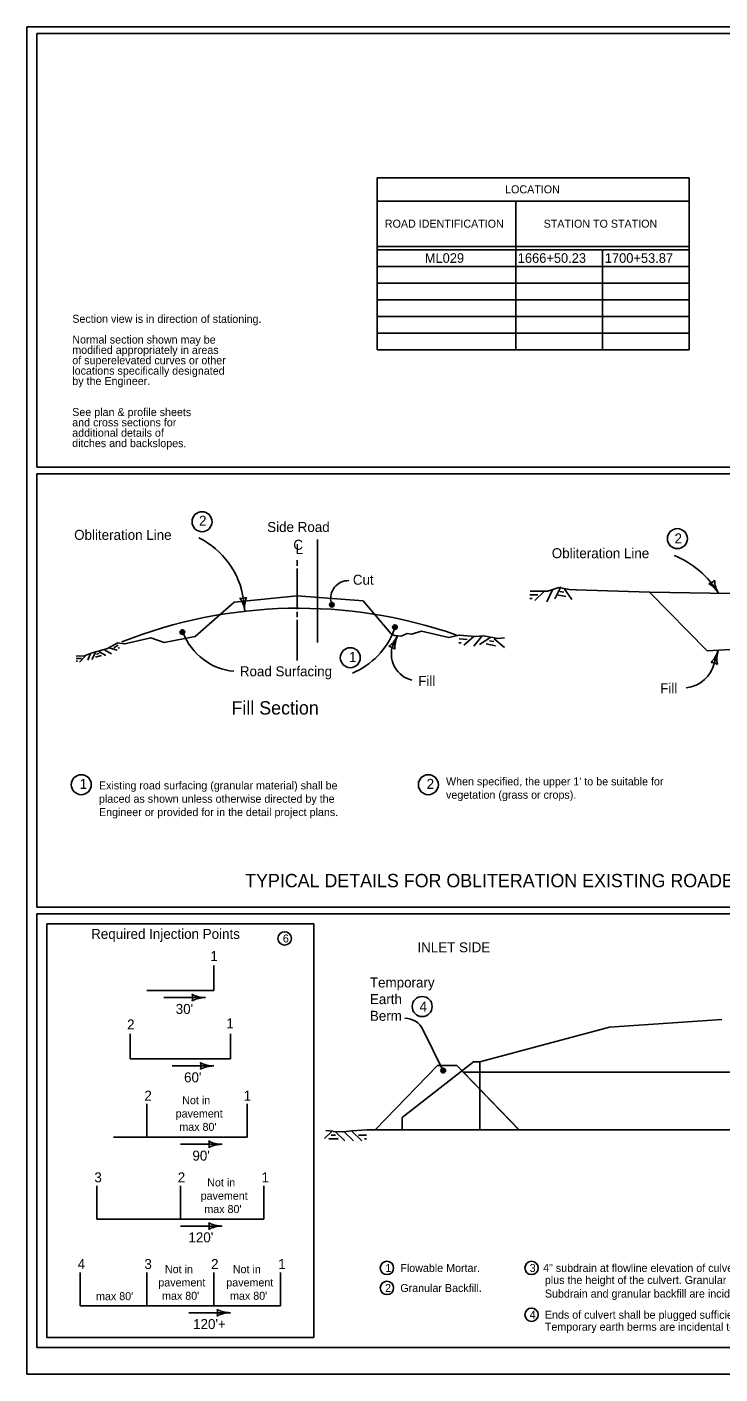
# Model space of a CAD drawing. Extents: x 10133 to 81668, y 7924 to 11018.
# Drawn here: x 10133 to 11172, y 7924 to 9944 of the extents above; entities that cross this region are included whole.
import ezdxf

# ---------------------------------------------------------------- set-up
doc = ezdxf.new("R2010")
doc.units = 0
for name, color, linetype in [('dsnCellElements', 7, 'Continuous'), ('DsnShtMinorGrid07', 7, 'Continuous'), ('DsnShtMinorGrid08', 7, 'Continuous'), ('DsnShtMinorGrid14', 7, 'Continuous'), ('Level 10', 7, 'Continuous'), ('Level 12', 7, 'Continuous'), ('Level 5', 7, 'Continuous'), ('Level 6', 7, 'Continuous'), ('Level 7', 7, 'Continuous'), ('Level 8', 7, 'Continuous'), ('SheetAddendum', 7, 'Continuous'), ('SheetBorder', 7, 'Continuous'), ('ShtPlotIdentification', 7, 'Continuous')]:
    doc.layers.add(name, color=color, linetype=linetype)

msp = doc.modelspace()

# ---------------------------------------------------------------- linework, layer by layer
at = {"layer": 'dsnCellElements'}
for p, q in [((10568, 9175.6), (10568, 9021.1)), ((10457.1, 9085.5), (10459.1, 9068.2)), ((10680.1, 9013.9), (10688, 9031)), ((11163.3, 8991.1), (11168.8, 9008.8)), ((10811.4, 8392.2), (11005.8, 8444.1)), ((11005.8, 8444.1), (11174.4, 8455.9)), ((10756.6, 8378.6), (10726.1, 8440.8)), ((10654.8, 8290.1), (10748.1, 8386.7)), ((10694.9, 8308.9), (10801.9, 8392.2)), ((10777.2, 8386.7), (10748.1, 8386.7)), ((10870.7, 8289.9), (10777.2, 8386.7)), ((10801.9, 8392.2), (10811.4, 8392.2)), ((10811.4, 8376.7), (10811.4, 8392.2)), ((10786.9, 8376.7), (11949.3, 8376.7)), ((10811.4, 8376.7), (10811.3, 8290.1)), ((10695, 8290), (10695, 8308.9)), ((10589.4, 8287.9), (10578.6, 8277.1)), ((10591.5, 8288), (10580.6, 8289)), ((10588.8, 8282.4), (10595.3, 8282.4)), ((10595.3, 8282.4), (10588.8, 8282.4)), ((10605.6, 8287.3), (10591.7, 8287.9)), ((10594.8, 8287.9), (10608.9, 8273.8)), ((10619.5, 8288.7), (10606.4, 8287.3)), ((10607.8, 8287.7), (10621.9, 8273.6)), ((10642.2, 8290.1), (10619.7, 8288.7)), ((10620.2, 8287.9), (10634.4, 8273.8)), ((10629.8, 8282.4), (10641.8, 8282.4)), ((10632.8, 8282.4), (10632.8, 8282.4)), ((10642.2, 8290.1), (12126.8, 8290.1)), ((10585, 8276.6), (10599.2, 8276.6)), ((10599.2, 8276.6), (10585, 8276.6)), ((10638.6, 8276.6), (10638.6, 8276.6)), ((10638.6, 8276.6), (10641.8, 8276.6))]:
    msp.add_line(p, q, dxfattribs=at)
for points in [[(10267.7, 9020.1), (10268.5, 9020.6), (10279.4, 9018.9), (10318.4, 9027.9), (10338, 9021), (10384.6, 9030), (10443.1, 9081.5), (10537.4, 9090.9), (10636.5, 9083.7), (10678.1, 9034.7), (10683.8, 9031.3), (10693.5, 9030.7), (10702.5, 9034.7), (10709.2, 9033.7), (10724, 9038.2), (10764.9, 9028.3), (10780.5, 9032), (10780.7, 9032)], [(10886.8, 9098.1), (10913.2, 9097.8), (10929.8, 9103.6), (10945.5, 9100.4), (10956, 9100.1)], [(10886.8, 9098.1), (10913.2, 9097.8), (10929.8, 9103.6), (10945.5, 9100.4), (10956.5, 9100.1)], [(10886.8, 9098.1), (10913.2, 9097.8), (10929.8, 9103.6), (10945.5, 9100.4), (10954.8, 9100.1)], [(10956, 9100.1), (11066, 9096.7), (11152.4, 9008.5), (11187.1, 9010.5), (11217.9, 9039), (11317.8, 9050.7), (11414.7, 9040.8), (11452.3, 9000.4), (11485.2, 8997.3), (11565.8, 9087.3), (11687.7, 9081.1)], [(10780.5, 9032), (10804.3, 9029.9), (10817.4, 9031.2), (10838, 9026.8), (10848.7, 9027.9)], [(10781.1, 9031.9), (10804.3, 9029.9), (10817.4, 9031.2), (10838, 9026.8), (10848.7, 9027.9)], [(10206.1, 9000.5), (10218.6, 9001), (10228.9, 9005), (10253.4, 9012.1), (10267.7, 9020.1)], [(10757, 8382.3), (10755.8, 8381.8), (10754, 8381.2), (10753.6, 8379.4), (10753.9, 8377.7), (10755.1, 8376.2), (10756.8, 8376.4), (10758.7, 8376.6), (10759.5, 8378.1), (10759.7, 8379.7), (10758.6, 8381.7), (10757.3, 8381.9), (10755.4, 8381.4), (10753.9, 8380.2), (10754, 8378.5), (10755.1, 8377.1), (10756.8, 8376.9), (10758.6, 8377.3), (10758.9, 8378.3), (10759.3, 8379.5), (10758.4, 8381.1), (10757.1, 8381), (10755.6, 8380.8), (10754.4, 8379.9), (10755, 8378.4), (10756.2, 8377.5), (10757.7, 8377.4), (10758.1, 8378.3), (10758.6, 8379.2), (10757.8, 8380.4), (10756.7, 8380.7), (10755.7, 8380.2), (10755.6, 8379), (10756.1, 8378.2), (10757.2, 8377.9), (10757.7, 8378.4), (10758, 8379), (10757.4, 8379.9), (10756.7, 8380.1), (10756, 8379.7), (10756.1, 8379), (10756.6, 8378.6), (10757.4, 8378.7), (10757.3, 8379.2), (10756.7, 8379.5)]]:
    msp.add_lwpolyline(points, dxfattribs=at)
for centre, radius in [((10518.9, 8577.2), 10), ((10725, 8475.1), 15), ((10756.7, 8379.1), 3.5), ((10672.3, 8083.1), 10), ((10889, 8083.1), 10), ((10672.3, 8053.1), 10), ((10889, 8013), 10)]:
    msp.add_circle(centre, radius, dxfattribs=at)
for centre, radius, start, end in [((10364.4, 8488.5), 16.4, 342.2666, 17.7333), ((10400, 8531), 42.5, 241.9275, 270), ((10400, 8446), 42.5, 90, 118.0725), ((10699.2, 8427.5), 30, 26.1603, 90), ((10376.9, 8386), 16.4, 342.2666, 17.7333), ((10412.5, 8428.5), 42.5, 241.9275, 270), ((10412.5, 8343.5), 42.5, 90, 118.0725), ((10592, 8292.9), 5, 264.4618, 267.1527), ((10605.9, 8292.2), 5, 267.1527, 275.9854), ((10620, 8283.7), 5, 93.5449, 95.9854), ((10389.4, 8268.5), 16.4, 342.2666, 17.7333), ((10425, 8311), 42.5, 241.9275, 270), ((10425, 8226), 42.5, 90, 118.0725), ((10389.4, 8146), 16.4, 342.2666, 17.7333), ((10425, 8188.5), 42.5, 241.9275, 270), ((10425, 8103.5), 42.5, 90, 118.0725), ((10401.9, 8016), 16.4, 342.2666, 17.7333), ((10437.5, 8058.5), 42.5, 241.9275, 270), ((10437.5, 7973.5), 42.5, 90, 118.0725)]:
    msp.add_arc(centre, radius, start, end, dxfattribs=at)
at = {"layer": 'DsnShtMinorGrid07'}
for p, q in [((10657.5, 9718), (11125.5, 9718)), ((10657.5, 9460), (10657.5, 9718)), ((11125.5, 9610), (11125.5, 9718)), ((10657.5, 9683), (11125.5, 9683)), ((10865.5, 9460), (10865.5, 9683)), ((10657.5, 9615), (11125.5, 9615)), ((10657.5, 9610), (10865.5, 9610)), ((10865.5, 9610), (10994.6, 9610)), ((10995.5, 9460), (10995.5, 9610)), ((10995.5, 9610), (11125.5, 9610)), ((11125.5, 9585), (11125.5, 9610)), ((10657.5, 9585), (11125.5, 9585)), ((11125.5, 9460), (11125.5, 9585)), ((10657.5, 9560), (11125.5, 9560)), ((10657.5, 9535), (11125.5, 9535)), ((10657.5, 9510), (11125.5, 9510)), ((10657.5, 9485), (11125.5, 9485)), ((10657.5, 9460), (11125.5, 9460))]:
    msp.add_line(p, q, dxfattribs=at)
at = {"layer": 'DsnShtMinorGrid08'}
msp.add_lwpolyline([(10147.5, 9934), (13252.5, 9934), (13252.5, 9284), (10147.5, 9284), (10147.5, 9934)], dxfattribs=at)
at = {"layer": 'Level 10'}
for centre, radius, start, end in [((10336.1, 9068.2), 122.3, 8.1205, 63.6379), ((11049.9, 9022), 140, 31.313, 67.8349), ((10614.6, 9086.9), 26.9, 88.6666, 193.1536), ((10451.4, 9068.1), 90.7, 201.1526, 264.3959), ((10577.1, 9079.5), 113, 292.5261, 339.8121), ((10718.8, 9003.6), 40, 165.0555, 256.3065), ((11116.2, 9001.1), 48.1, 275.6798, 348.0251)]:
    msp.add_arc(centre, radius, start, end, dxfattribs=at)
at = {"layer": 'Level 12'}
for points in [[(10147.5, 8614), (13252.5, 8614), (13252.5, 7964), (10147.5, 7964), (10147.5, 8614)], [(10811.4, 8376.7), (10786.9, 8376.7), (10811.4, 8351.4), (10811.4, 8376.7)]]:
    msp.add_lwpolyline(points, dxfattribs=at)
for points in [[(10777.2, 8386.7), (10748.1, 8386.7), (10654.8, 8290.1), (10811.3, 8290.1), (10811.4, 8351.4)], [(10777.2, 8386.7), (10748.1, 8386.7), (10654.8, 8290.1), (10811.3, 8290.1), (10811.4, 8351.4)], [(11920.8, 8335.4), (11920.8, 8376.7), (10811.4, 8376.7), (10811.4, 8351.4), (10870.5, 8290.1), (11788.7, 8290.1), (11807.3, 8309.3), (11895.6, 8309.3)], [(10811.3, 8290.1), (10870.5, 8290.1), (10811.4, 8351.4)]]:
    msp.add_lwpolyline(points, close=True, dxfattribs=at)
msp.add_circle((10756.7, 8379.1), 3.5, dxfattribs=at)
msp.add_circle((10756.7, 8379.1), 3.5, dxfattribs=at)
at = {"layer": 'Level 5'}
for points in [[(10147.5, 9274), (11692.5, 9274), (11692.5, 8624), (10147.5, 8624), (10147.5, 9274)], [(10589.3, 9074.5), (10590.5, 9075), (10592.4, 9075.6), (10592.7, 9077.4), (10592.5, 9079.1), (10591.3, 9080.6), (10589.5, 9080.4), (10587.7, 9080.2), (10586.8, 9078.7), (10586.7, 9077.1), (10587.7, 9075.1), (10589.1, 9075), (10590.9, 9075.4), (10592.4, 9076.6), (10592.4, 9078.3), (10591.2, 9079.7), (10589.6, 9079.9), (10587.7, 9079.5), (10587.4, 9078.5), (10587.1, 9077.3), (10587.9, 9075.7), (10589.3, 9075.8), (10590.8, 9076), (10591.9, 9076.9), (10591.4, 9078.4), (10590.2, 9079.3), (10588.6, 9079.4), (10588.3, 9078.5), (10587.8, 9077.6), (10588.5, 9076.4), (10589.7, 9076.1), (10590.7, 9076.6), (10590.8, 9077.8), (10590.2, 9078.6), (10589.2, 9078.9), (10588.7, 9078.4), (10588.4, 9077.8), (10588.9, 9076.9), (10589.7, 9076.7), (10590.4, 9077.2), (10590.2, 9077.8), (10589.7, 9078.2), (10589, 9078.1), (10589, 9077.6), (10589.6, 9077.3)], [(10365.2, 9033.5), (10366.4, 9034.1), (10368.2, 9034.6), (10368.6, 9036.5), (10368.3, 9038.1), (10367.2, 9039.6), (10365.4, 9039.5), (10363.6, 9039.2), (10362.7, 9037.8), (10362.5, 9036.2), (10363.6, 9034.2), (10365, 9034), (10366.8, 9034.5), (10368.3, 9035.7), (10368.3, 9037.4), (10367.1, 9038.8), (10365.4, 9039), (10363.6, 9038.6), (10363.3, 9037.6), (10362.9, 9036.3), (10363.8, 9034.8), (10365.1, 9034.9), (10366.7, 9035.1), (10367.8, 9036), (10367.2, 9037.5), (10366.1, 9038.4), (10364.5, 9038.4), (10364.1, 9037.6), (10363.7, 9036.7), (10364.4, 9035.4), (10365.6, 9035.2), (10366.6, 9035.7), (10366.6, 9036.8), (10366.1, 9037.7), (10365.1, 9037.9), (10364.6, 9037.5), (10364.3, 9036.9), (10364.8, 9036), (10365.5, 9035.8), (10366.2, 9036.2), (10366.1, 9036.8), (10365.6, 9037.2), (10364.9, 9037.2), (10364.9, 9036.7), (10365.5, 9036.4)], [(10684, 9040.8), (10685.2, 9041.3), (10687, 9041.9), (10687.4, 9043.8), (10687.1, 9045.4), (10685.9, 9046.9), (10684.2, 9046.8), (10682.4, 9046.5), (10681.5, 9045), (10681.3, 9043.5), (10682.4, 9041.5), (10683.7, 9041.3), (10685.6, 9041.8), (10687.1, 9042.9), (10687, 9044.7), (10685.9, 9046.1), (10684.2, 9046.2), (10682.4, 9045.9), (10682.1, 9044.8), (10681.7, 9043.6), (10682.6, 9042.1), (10683.9, 9042.1), (10685.5, 9042.4), (10686.6, 9043.2), (10686, 9044.8), (10684.8, 9045.6), (10683.3, 9045.7), (10682.9, 9044.9), (10682.4, 9043.9), (10683.2, 9042.7), (10684.3, 9042.4), (10685.3, 9043), (10685.4, 9044.1), (10684.9, 9044.9), (10683.8, 9045.2), (10683.3, 9044.8), (10683, 9044.2), (10683.6, 9043.2), (10684.3, 9043.1), (10685, 9043.5), (10684.9, 9044.1), (10684.4, 9044.5), (10683.6, 9044.5), (10683.7, 9044), (10684.3, 9043.7)]]:
    msp.add_lwpolyline(points, dxfattribs=at)
for centre, radius in [((10395, 9202.1), 15), ((11107.7, 9176.7), 15), ((10589.6, 9077.7), 3.5), ((10365.5, 9036.7), 3.5), ((10684.3, 9044), 3.5), ((10617.3, 8998.2), 15), ((10214, 8807.8), 15), ((10734.3, 8807.8), 15)]:
    msp.add_circle(centre, radius, dxfattribs=at)
for centre, radius, start, end in [((11151, 9125.2), 16.4, 283.5797, 319.0464), ((11205.8, 9116.8), 42.5, 183.2405, 211.313), ((11133.2, 9072.7), 42.5, 31.313, 59.3855), ((10455, 9103.6), 16.4, 258.8775, 294.3443), ((10416.9, 9063.3), 42.5, 6.6109, 34.6834), ((10501.3, 9073.1), 42.5, 158.5384, 186.6109), ((10649.3, 9048.7), 42.5, 307.3638, 335.4363), ((10726.6, 9013.4), 42.5, 155.4363, 183.5088), ((10673.2, 8998.6), 16.4, 47.7029, 83.1696), ((11128.2, 9021.4), 42.5, 314.7357, 342.8082), ((11158.3, 8974.8), 16.4, 55.0749, 90.5416), ((11209.4, 8996.3), 42.5, 162.8082, 190.8807)]:
    msp.add_arc(centre, radius, start, end, dxfattribs=at)
at = {"layer": 'SheetAddendum'}
for p, q in [((10908.4, 9097.8), (10894.1, 9083.9)), ((10920.5, 9100.1), (10911.8, 9082.1)), ((10932.7, 9104.6), (10924, 9086.6)), ((10938.1, 9101.9), (10949.2, 9085.3)), ((10802.7, 9030.1), (10787.4, 9017.2)), ((10815.1, 9030.8), (10802.4, 9015.3)), ((10247.7, 9010.3), (10259.2, 9003.9)), ((10255.3, 9013.2), (10268, 9009.6)), ((10827.8, 9029), (10811, 9018.1)), ((10833, 9026.3), (10848.5, 9013.7)), ((10220.3, 9001), (10211.4, 8991.4)), ((10227.9, 9004.4), (10223.6, 8994.6)), ((10236, 9007.1), (10229.7, 8995.5)), ((10239.4, 9008), (10251, 9001.7))]:
    msp.add_line(p, q, dxfattribs=at)
for points in [[(10886.7, 9092.7), (10898.7, 9092.5)], [(10927.6, 9092.4), (10940.2, 9089.9)], [(10931.2, 9097.7), (10937.6, 9096.4)], [(10886.6, 9086.9), (10889.9, 9086.8)], [(10262.6, 9013.1), (10269.5, 9017)], [(10269.5, 9012.6), (10271.3, 9013.7)], [(10780.2, 9020.7), (10783.4, 9020.4)], [(10780.7, 9026.5), (10792.6, 9025.4)], [(10821.1, 9018.8), (10835, 9015.8)], [(10826.1, 9023.7), (10832.5, 9022.4)], [(10206.3, 8996.9), (10214.2, 8997.2)], [(10206.4, 8993.1), (10208.5, 8993.2)], [(10235.3, 8999.1), (10244.3, 9001.7)], [(10236.7, 9003.5), (10240.8, 9004.7)]]:
    msp.add_lwpolyline(points, dxfattribs=at)
at = {"layer": 'SheetBorder'}
msp.add_lwpolyline([(10132.5, 9944), (13267.5, 9944), (13267.5, 7924), (10132.5, 7924)], close=True, dxfattribs=at)
at = {"layer": 'ShtPlotIdentification'}
for p, q in [((11066, 9096.7), (11565.8, 9087.3)), ((10412.5, 8499), (10412.5, 8536.5)), ((10312.5, 8499), (10412.5, 8499)), ((10337.5, 8488.5), (10400, 8488.5)), ((10287.5, 8396.5), (10287.5, 8434)), ((10437.5, 8396.5), (10437.5, 8434)), ((10287.5, 8396.5), (10437.5, 8396.5)), ((10350, 8386), (10412.5, 8386)), ((10312.5, 8279), (10312.5, 8329)), ((10462.5, 8279), (10462.5, 8329)), ((10262.5, 8279), (10462.5, 8279)), ((10362.5, 8268.5), (10425, 8268.5)), ((10237.5, 8156.5), (10237.5, 8206.5)), ((10362.5, 8156.5), (10362.5, 8206.5)), ((10487.5, 8156.5), (10487.5, 8206.5)), ((10237.5, 8156.5), (10487.5, 8156.5)), ((10362.5, 8146), (10425, 8146)), ((10212.5, 8026.5), (10212.5, 8076.5)), ((10312.5, 8026.5), (10312.5, 8076.5)), ((10412.5, 8026.5), (10412.5, 8076.5)), ((10512.5, 8026.5), (10512.5, 8076.5)), ((10212.5, 8026.5), (10512.5, 8026.5)), ((10375, 8016), (10437.5, 8016))]:
    msp.add_line(p, q, dxfattribs=at)
for points in [[(10537.4, 9136.2), (10537.4, 9144.3)], [(10537.4, 9071.1), (10537.4, 9132.1)], [(10537.4, 9058.9), (10537.4, 9067.1)], [(10537.4, 8993.9), (10537.4, 9054.9)]]:
    msp.add_lwpolyline(points, dxfattribs=at)
msp.add_lwpolyline([(10162.5, 7979), (10562.5, 7979), (10562.5, 8599), (10162.5, 8599)], close=True, dxfattribs=at)
for centre, radius, start, end in [((10539.4, 8353.7), 718.7, 70.7273, 111.6141), ((10614.6, 9086.9), 26.9, 198.1595, 198.2767), ((10336.1, 9068.2), 122.3, 359.276, 359.2887)]:
    msp.add_arc(centre, radius, start, end, dxfattribs=at)

# ---------------------------------------------------------------- texts
at = {"layer": 'DsnShtMinorGrid07'}
for s, p in [('LOCATION', (10849.4, 9694.5)), ('ROAD IDENTIFICATION', (10669.1, 9643)), ('STATION TO STATION', (10907.2, 9643))]:
    msp.add_text(s, height=12, dxfattribs=at).set_placement(p)
at = {"layer": 'DsnShtMinorGrid14'}
for s, p in [('Section view is in direction of stationing.', (10200.5, 9500.4)), ('Normal section shown may be', (10200.5, 9469.3)), ('modified appropriately in areas', (10200.5, 9453.8)), ('of superelevated curves or other', (10200.5, 9438.3)), ('locations specifically designated', (10200.5, 9422.7)), ('by the Engineer.', (10200.5, 9407.2)), ('See plan & profile sheets', (10200.4, 9360.6)), ('and cross sections for', (10200.4, 9345.1)), ('additional details of', (10200.4, 9329.6)), ('ditches and backslopes.', (10200.4, 9314))]:
    msp.add_text(s, height=12, rotation=359.9583, dxfattribs=at).set_placement(p)
at = {"layer": 'Level 6'}
for s, p in [('Fill Section', (10439.2, 8913)), ('TYPICAL DETAILS FOR OBLITERATION EXISTING ROADBED', (10459.7, 8654))]:
    msp.add_text(s, height=19.999, dxfattribs=at).set_placement(p)
at = {"layer": 'Level 7'}
for s, p in [('2', (10390.5, 9196)), ('Side Road', (10492.7, 9186.7)), ('Obliteration Line', (10203.3, 9174.9)), ('C', (10531.9, 9160)), ('2', (11103.4, 9169.5)), ('L', (10535.4, 9153.7)), ('Obliteration Line', (10919.4, 9147.4)), ('Cut', (10621.1, 9107.6)), ('1', (10615.3, 8991.6)), ('Road Surfacing', (10451.7, 8970.3)), ('Fill', (10719.1, 8955.9)), ('Fill', (11081.9, 8944.8)), ('1', (10211.5, 8801.5)), ('2', (10731.8, 8801.5))]:
    msp.add_text(s, height=15, dxfattribs=at).set_placement(p)
at = {"layer": 'Level 8'}
for s, p in [('Existing road surfacing (granular material) shall be', (10240.5, 8800.7)), ("When specified, the upper 1' to be suitable for", (10760.8, 8806.7)), ('placed as shown unless otherwise directed by the', (10240.5, 8780.7)), ('vegetation (grass or crops).', (10760.8, 8786.7)), ('Engineer or provided for in the detail project plans.', (10240.5, 8760.7))]:
    msp.add_text(s, height=12, dxfattribs=at).set_placement(p)
at = {"layer": 'SheetBorder'}
for s, p in [('ML029', (10729, 9590.3)), ('1666+50.23', (10868.4, 9590.3)), ('1700+53.87', (10998.9, 9590.3))]:
    msp.add_text(s, height=14.4, dxfattribs=at).set_placement(p)
at = {"layer": 'ShtPlotIdentification'}
for s, height, rotation, p in [('Required Injection Points', 15, 359.9817, (10228.8, 8576.6)), ('6', 12, 359.9815, (10516.2, 8571.2)), ('INLET SIDE', 15, 0.0185, (10717.9, 8556.4)), ('1', 15, 359.9815, (10407.4, 8543.2)), ('Temporary ', 15, 0.0185, (10646.7, 8503.7)), ('Earth ', 15, 0.0185, (10646.7, 8478.7)), ("30'", 15, 359.9815, (10355.6, 8464)), ('Berm', 15, 0.0185, (10646.7, 8453.7)), ('4', 15, 0.0185, (10721.1, 8467.6)), ('2', 15, 359.9815, (10282.7, 8440.7)), ('1', 15, 359.9815, (10431.5, 8442.5)), ("60'", 15, 359.9815, (10368.1, 8361.5)), ('2', 15, 359.9815, (10308.6, 8334)), ('1', 15, 359.9815, (10457.4, 8334)), ('Not in', 12, 359.9815, (10365.3, 8328.7)), ('pavement', 12, 359.9815, (10355.5, 8308.7)), ("max 80'", 12, 359.9815, (10361, 8288.7)), ("90'", 15, 359.9815, (10380.6, 8244)), ('3', 15, 359.9815, (10233.6, 8211.5)), ('2', 15, 359.9815, (10358.6, 8211.5)), ('1', 15, 359.9815, (10484.2, 8211.5)), ('Not in', 12, 359.9815, (10402.8, 8205.3)), ('pavement', 12, 359.9815, (10393, 8185.4)), ("max 80'", 12, 359.9815, (10398.5, 8165.4)), ("120'", 15, 359.9815, (10374.6, 8121.5)), ('4', 15, 359.9815, (10208.6, 8081.5)), ('3', 15, 359.9815, (10308.6, 8081.5)), ('Not in', 12, 359.9815, (10339.4, 8075.3)), ('2', 15, 359.9815, (10408.6, 8081.5)), ('Not in', 12, 359.9815, (10441.2, 8075.3)), ('1', 15, 359.9815, (10509.2, 8081.5)), ('1', 12, 359.9815, (10669.9, 8077.1)), ('Flowable Mortar.', 12, 359.9817, (10692.3, 8077.1)), ('3', 12, 359.9791, (10886.2, 8077.1)), ('pavement', 12, 359.9815, (10329.5, 8055.4)), ('pavement', 12, 359.9815, (10431.4, 8055.4)), ("max 80'", 12, 359.9815, (10236.1, 8034.8)), ("max 80'", 12, 359.9815, (10335.1, 8035.4)), ("max 80'", 12, 359.9815, (10437, 8035.4)), ('2', 12, 359.9817, (10669.5, 8047.1)), ('Granular Backfill.', 12, 359.9806, (10692.3, 8047.1)), ('Ends of culvert shall be plugged sufficiently to retain flowable mortar.', 12, 359.9815, (10909, 8007)), ("120'+", 15, 359.9815, (10381.6, 7991.5)), ('4', 12, 359.9815, (10886.2, 8007)), ('Temporary earth berms are incidental to flowable mortar.', 12, 359.9815, (10909, 7989))]:
    msp.add_text(s, height=height, rotation=rotation, dxfattribs=at).set_placement(p)
for s, p in [('4" subdrain at flowline elevation of culvert shall be extended into the culvert a distance of 2\'  ', (10906.4, 8077.1)), ("plus the height of the culvert. Granular Backfill covers subdrain and extends an additional 2'.", (10909, 8059.1)), ('Subdrain and granular backfill are incidental to flowable mortar.', (10909, 8038.7))]:
    msp.add_text(s, height=12, dxfattribs=at).set_placement(p)

doc.saveas('drawing.dxf')
